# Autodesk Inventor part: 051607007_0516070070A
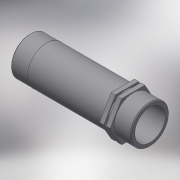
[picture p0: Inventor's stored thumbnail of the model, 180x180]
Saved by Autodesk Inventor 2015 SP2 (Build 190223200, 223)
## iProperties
Created: 2017-05
Part Number: 051607007_0516070070A
Material: Generic
Description: PLASSON RISER 3/4"-3/4"
Document SubType Name: Modeling
Designer: KIM
Mass: 20.3153 g
Surface Area: 184.457 cm^2
Volume: 20.3153 cm^3
Density: 1 g/cm^3
Appearance: Default
Author: KIM
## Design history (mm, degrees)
derived "051607.ipt"
feature "Solid1::051607.ipt"
tag "TaggingFeature1"
body "Solid1"
other parameters: "d0" = 113, "d1" = 26.441, "d2" = 27, "d3" = 16.764, "d5" = 18, "d6" = 4.5, "d8" = 0.9, "d12" = 0, "d13" = 2.25, "d15" = 18, "d17" = 0, "d18" = 20.955, "H_" = 113, "R_" = 26.441, "E_" = 27, "l_2" = 18, "R_1" = 20.955
